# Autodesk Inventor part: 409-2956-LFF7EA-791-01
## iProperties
Shininess: 64.0
Angle Display Precision: 2
Document Length Units: 11272
Document Angle Units: 11279
Document Time Units: 11290
Document Mass Units: 11286
Document Length Units Precision: 3
Document Angle Units Precision: 2
Compacted: True
Created: 2002-04
Part Number: 409-2956-LFF7EA-791-01
Description: DISCHARGE PIPE STAND ANGLE
Document SubType Name: Modeling
Designer: S. Boerckel
Mass: 4204.36 g
Surface Area: 1754.47 cm^2
Volume: 535.587 cm^3
Density: 7.85 g/cm^3
Cost Center: 2 x 2 x 1/4 ANGLE
Material: ASTM A36
Engineer: S. Boerckel
User Status: SAW
Density: 0.0
Volumn: 0.0
Area: 0.0
PropertySet Name: Model Information
Control State: 0
Master: False
Checked Out: False
length: 34.940 in
SMR: =<COST CENTER> - <MATERIAL>
Author: S. Boerckel
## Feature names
1. Extrusion1
